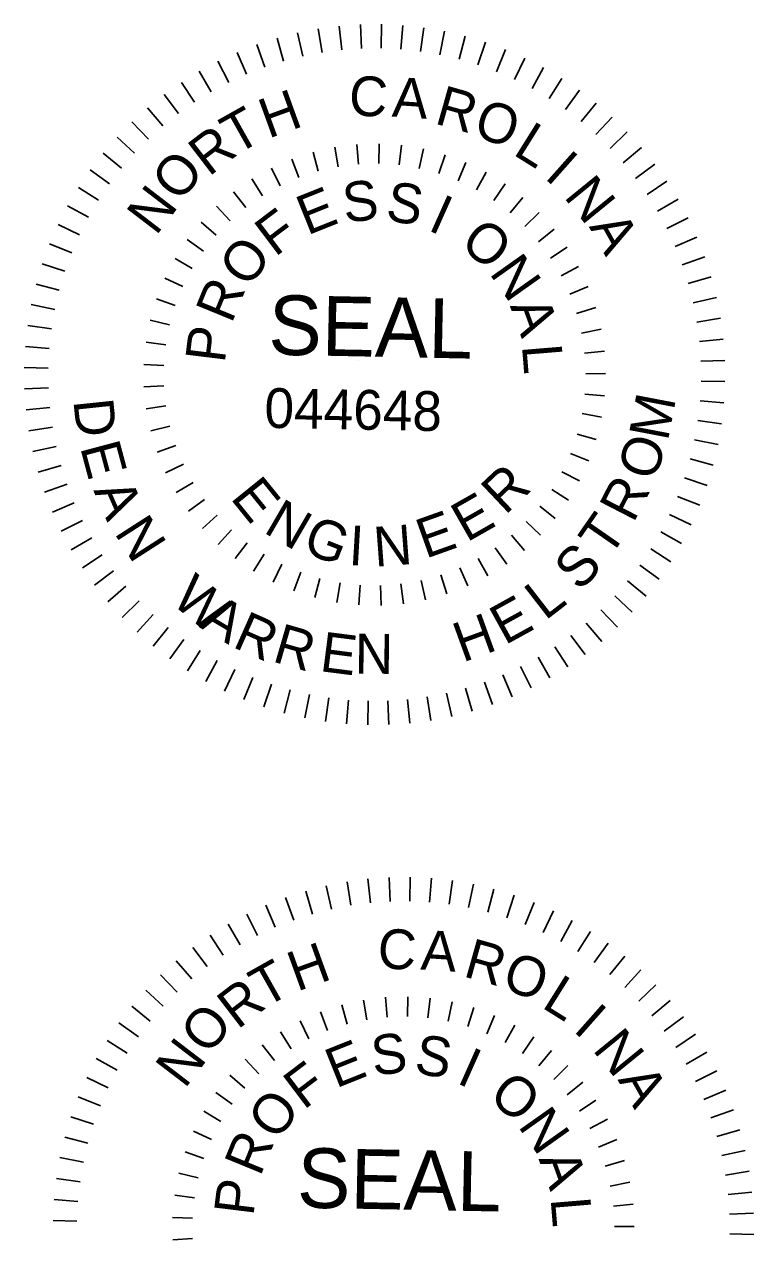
# Model space of a CAD drawing. Extents: x 0 to 4772457, y -312190 to 1506.
# Drawn here: x 3.6853 to 3.812, y 1.4541 to 1.6653 of the extents above; entities that cross this region are included whole.
import ezdxf

# ---------------------------------------------------------------- set-up
doc = ezdxf.new("R2010")
doc.units = 0
doc.layers.add('Phasing Diagram CELL', color=7, linetype='Continuous')

msp = doc.modelspace()

# ---------------------------------------------------------------- linework, layer by layer
at = {"layer": 'Phasing Diagram CELL'}
for p, q in [((3.73639, 1.66449), (3.73706, 1.6604)), ((3.74004, 1.66497), (3.74045, 1.66085)), ((3.7437, 1.66523), (3.74387, 1.66109)), ((3.74738, 1.66527), (3.7473, 1.66112)), ((3.75106, 1.66508), (3.75073, 1.66095)), ((3.75471, 1.66468), (3.75413, 1.66057)), ((3.75833, 1.66406), (3.7575, 1.65999)), ((3.72922, 1.66288), (3.73037, 1.65888)), ((3.73279, 1.66379), (3.73369, 1.65974)), ((3.76191, 1.66322), (3.76084, 1.65921)), ((3.76544, 1.66216), (3.76412, 1.65822)), ((3.7223, 1.6604), (3.72392, 1.65659)), ((3.72572, 1.66175), (3.72712, 1.65783)), ((3.76888, 1.66089), (3.76733, 1.65704)), ((3.71896, 1.65886), (3.72082, 1.65515)), ((3.77225, 1.65941), (3.77048, 1.65566)), ((3.77552, 1.65774), (3.77352, 1.6541)), ((3.71572, 1.65712), (3.7178, 1.65353)), ((3.77869, 1.65587), (3.77647, 1.65236)), ((3.7126, 1.65518), (3.71489, 1.65172)), ((3.78174, 1.65381), (3.77931, 1.65045)), ((3.7096, 1.65306), (3.71209, 1.64975)), ((3.78465, 1.65158), (3.78203, 1.64836)), ((3.70672, 1.65076), (3.70941, 1.64761)), ((3.78743, 1.64916), (3.78462, 1.64612)), ((3.704, 1.6483), (3.70687, 1.64531)), ((3.70143, 1.64567), (3.70447, 1.64286)), ((3.79006, 1.64659), (3.78707, 1.64372)), ((3.69901, 1.64289), (3.70223, 1.64027)), ((3.73547, 1.64308), (3.73639, 1.63974)), ((3.73925, 1.64393), (3.73984, 1.64052)), ((3.74309, 1.64441), (3.74336, 1.64097)), ((3.74697, 1.64452), (3.7469, 1.64107)), ((3.7469, 1.64107), (3.74697, 1.64452)), ((3.75084, 1.64426), (3.75044, 1.64083)), ((3.75466, 1.64362), (3.75393, 1.64024)), ((3.79252, 1.64387), (3.78937, 1.64118)), ((3.73179, 1.64186), (3.73303, 1.63863)), ((3.7584, 1.64262), (3.75735, 1.63933)), ((3.76204, 1.64127), (3.76067, 1.63809)), ((3.79483, 1.64099), (3.79151, 1.6385)), ((3.69678, 1.63998), (3.70014, 1.63755)), ((3.72824, 1.6403), (3.72978, 1.63721)), ((3.76552, 1.63956), (3.76386, 1.63653)), ((3.69472, 1.63693), (3.69823, 1.63471)), ((3.72486, 1.6384), (3.7267, 1.63547)), ((3.76882, 1.63753), (3.76687, 1.63467)), ((3.79694, 1.63799), (3.79349, 1.6357)), ((3.72168, 1.63618), (3.72379, 1.63344)), ((3.77191, 1.63519), (3.76969, 1.63253)), ((3.79888, 1.63487), (3.79529, 1.63279)), ((3.69285, 1.63376), (3.69649, 1.63176)), ((3.71873, 1.63367), (3.7211, 1.63115)), ((3.77476, 1.63256), (3.77229, 1.63013)), ((3.69118, 1.63049), (3.69493, 1.62871)), ((3.71603, 1.63089), (3.71863, 1.62861)), ((3.80062, 1.63163), (3.79691, 1.62977)), ((3.77734, 1.62967), (3.77466, 1.6275)), ((3.80216, 1.62829), (3.79835, 1.62667)), ((3.6897, 1.62712), (3.69355, 1.62557)), ((3.71362, 1.62786), (3.71642, 1.62583)), ((3.77964, 1.62655), (3.77675, 1.62463)), ((3.71151, 1.62461), (3.71449, 1.62286)), ((3.80351, 1.62487), (3.7996, 1.62347)), ((3.68843, 1.62367), (3.69237, 1.62236)), ((3.78161, 1.62322), (3.77856, 1.62159)), ((3.68737, 1.62015), (3.69138, 1.61908)), ((3.70972, 1.62116), (3.71286, 1.61972)), ((3.78327, 1.6197), (3.78007, 1.61839)), ((3.80464, 1.62137), (3.80065, 1.62022)), ((3.70828, 1.61756), (3.71155, 1.61643)), ((3.80555, 1.6178), (3.80151, 1.6169)), ((3.68653, 1.61657), (3.6906, 1.61574)), ((3.78457, 1.61605), (3.78125, 1.61505)), ((3.70718, 1.61385), (3.71054, 1.61303)), ((3.80625, 1.6142), (3.80216, 1.61353)), ((3.68591, 1.61295), (3.69002, 1.61237)), ((3.78551, 1.61229), (3.78212, 1.61162)), ((3.68551, 1.60929), (3.68964, 1.60896)), ((3.70646, 1.61004), (3.70988, 1.60956)), ((3.80673, 1.61055), (3.80261, 1.61014)), ((3.78609, 1.60846), (3.78265, 1.60812)), ((3.80699, 1.60689), (3.80285, 1.60672)), ((3.68532, 1.60562), (3.68947, 1.60554)), ((3.7061, 1.60618), (3.70955, 1.60602)), ((3.74334, 1.60681), (3.74334, 1.60681)), ((3.78629, 1.60459), (3.78284, 1.60457)), ((3.80703, 1.60321), (3.80288, 1.60329)), ((3.68536, 1.60194), (3.6895, 1.60211)), ((3.70611, 1.6023), (3.70956, 1.60248)), ((3.78612, 1.60072), (3.78268, 1.60103)), ((3.68562, 1.59828), (3.68974, 1.59869)), ((3.70651, 1.59845), (3.70992, 1.59896)), ((3.80685, 1.59953), (3.80271, 1.59986)), ((3.7822, 1.59765), (3.7856, 1.59701)), ((3.80644, 1.59588), (3.80234, 1.59646)), ((3.6861, 1.59463), (3.69019, 1.5953)), ((3.70727, 1.59464), (3.71062, 1.59548)), ((3.70839, 1.59093), (3.71165, 1.59209)), ((3.78467, 1.59311), (3.78135, 1.59408)), ((3.80582, 1.59226), (3.80175, 1.59309)), ((3.6868, 1.59103), (3.69085, 1.59193)), ((3.7834, 1.58945), (3.78019, 1.59073)), ((3.68771, 1.58746), (3.69171, 1.58861)), ((3.70987, 1.58735), (3.713, 1.58883)), ((3.80498, 1.58868), (3.80097, 1.58975)), ((3.78177, 1.58593), (3.77871, 1.58752)), ((3.80392, 1.58515), (3.79998, 1.58647)), ((3.68884, 1.58396), (3.69276, 1.58536)), ((3.71168, 1.58393), (3.71466, 1.58569)), ((3.77983, 1.58258), (3.77693, 1.58446)), ((3.69019, 1.58054), (3.694, 1.58216)), ((3.71382, 1.58069), (3.71661, 1.58274)), ((3.77756, 1.57943), (3.77486, 1.58158)), ((3.80265, 1.58171), (3.7988, 1.58326)), ((3.71627, 1.57768), (3.71884, 1.57998)), ((3.80117, 1.57834), (3.79742, 1.58011)), ((3.69173, 1.5772), (3.69544, 1.57906)), ((3.71898, 1.57492), (3.72133, 1.57746)), ((3.775, 1.57652), (3.77252, 1.57892)), ((3.69347, 1.57396), (3.69706, 1.57604)), ((3.72196, 1.57244), (3.72404, 1.57519)), ((3.77218, 1.57387), (3.76994, 1.5765)), ((3.7995, 1.57507), (3.79586, 1.57707)), ((3.69541, 1.57084), (3.69887, 1.57312)), ((3.72515, 1.57025), (3.72697, 1.57319)), ((3.76911, 1.5715), (3.76713, 1.57434)), ((3.79763, 1.5719), (3.79413, 1.57412)), ((3.72856, 1.56838), (3.73007, 1.57149)), ((3.76583, 1.56944), (3.76413, 1.57246)), ((3.79557, 1.56885), (3.79221, 1.57128)), ((3.69753, 1.56784), (3.70084, 1.57033)), ((3.73212, 1.56684), (3.73333, 1.57008)), ((3.73668, 1.56901), (3.73578, 1.56566)), ((3.75873, 1.56631), (3.75765, 1.5696)), ((3.76235, 1.56771), (3.76096, 1.57087)), ((3.69983, 1.56496), (3.70298, 1.56765)), ((3.7396, 1.56484), (3.74016, 1.56825)), ((3.74344, 1.56439), (3.74368, 1.56784)), ((3.74732, 1.56431), (3.74722, 1.56777)), ((3.75118, 1.56461), (3.75075, 1.56804)), ((3.755, 1.56528), (3.75424, 1.56866)), ((3.79334, 1.56594), (3.79012, 1.56856)), ((3.70229, 1.56224), (3.70528, 1.56511)), ((3.79092, 1.56316), (3.78788, 1.56597)), ((3.70492, 1.55966), (3.70773, 1.56271)), ((3.78835, 1.56053), (3.78548, 1.56352)), ((3.7077, 1.55725), (3.71032, 1.56047)), ((3.78563, 1.55807), (3.78294, 1.56122)), ((3.71061, 1.55502), (3.71304, 1.55838)), ((3.78275, 1.55577), (3.78026, 1.55908)), ((3.71366, 1.55296), (3.71588, 1.55646)), ((3.77975, 1.55365), (3.77747, 1.5571)), ((3.71683, 1.55109), (3.71883, 1.55473)), ((3.77663, 1.55171), (3.77455, 1.5553)), ((3.7201, 1.54942), (3.72188, 1.55317)), ((3.77005, 1.54843), (3.76843, 1.55224)), ((3.77339, 1.54997), (3.77153, 1.55368)), ((3.72347, 1.54794), (3.72502, 1.55179)), ((3.72692, 1.54667), (3.72823, 1.55061)), ((3.76313, 1.54595), (3.76198, 1.54994)), ((3.76663, 1.54708), (3.76523, 1.55099)), ((3.73044, 1.54561), (3.73151, 1.54962)), ((3.73402, 1.54477), (3.73485, 1.54884)), ((3.73764, 1.54415), (3.73822, 1.54825)), ((3.7413, 1.54374), (3.74163, 1.54788)), ((3.74865, 1.5436), (3.74848, 1.54774)), ((3.75231, 1.54386), (3.7519, 1.54798)), ((3.75596, 1.54434), (3.75529, 1.54843)), ((3.75957, 1.54504), (3.75866, 1.54908)), ((3.74497, 1.54356), (3.74505, 1.54771)), ((3.74138, 1.51631), (3.74204, 1.51222)), ((3.74502, 1.51679), (3.74544, 1.51266)), ((3.74869, 1.51705), (3.74885, 1.5129)), ((3.75237, 1.51709), (3.75228, 1.51294)), ((3.75604, 1.5169), (3.75571, 1.51277)), ((3.75969, 1.5165), (3.75912, 1.51239)), ((3.7342, 1.51469), (3.73536, 1.5107)), ((3.73777, 1.51561), (3.73868, 1.51156)), ((3.76332, 1.51588), (3.76249, 1.51181)), ((3.76689, 1.51503), (3.76583, 1.51102)), ((3.77042, 1.51398), (3.76911, 1.51003)), ((3.72729, 1.51222), (3.72891, 1.5084)), ((3.73071, 1.51356), (3.73211, 1.50965)), ((3.77387, 1.51271), (3.77232, 1.50886)), ((3.72395, 1.51068), (3.7258, 1.50696)), ((3.77723, 1.51123), (3.77546, 1.50748)), ((3.72071, 1.50893), (3.72279, 1.50534)), ((3.78051, 1.50956), (3.77851, 1.50592)), ((3.78368, 1.50769), (3.78146, 1.50418)), ((3.71758, 1.507), (3.71987, 1.50354)), ((3.78672, 1.50563), (3.7843, 1.50226)), ((3.71458, 1.50488), (3.71707, 1.50157)), ((3.78964, 1.50339), (3.78702, 1.50018)), ((3.71171, 1.50258), (3.7144, 1.49942)), ((3.70898, 1.50011), (3.71186, 1.49712)), ((3.79242, 1.50098), (3.78961, 1.49793)), ((3.70641, 1.49749), (3.70946, 1.49468)), ((3.79504, 1.49841), (3.79205, 1.49554)), ((3.74424, 1.49575), (3.74483, 1.49234)), ((3.74808, 1.49623), (3.74834, 1.49278)), ((3.75196, 1.49634), (3.75189, 1.49289)), ((3.75189, 1.49289), (3.75196, 1.49634)), ((3.75583, 1.49607), (3.75542, 1.49264)), ((3.75965, 1.49544), (3.75892, 1.49206)), ((3.79751, 1.49568), (3.79435, 1.493)), ((3.704, 1.49471), (3.70721, 1.49209)), ((3.73677, 1.49368), (3.73801, 1.49045)), ((3.74046, 1.4949), (3.74138, 1.49156)), ((3.76339, 1.49444), (3.76234, 1.49114)), ((3.76702, 1.49308), (3.76566, 1.4899)), ((3.70176, 1.4918), (3.70513, 1.48937)), ((3.73323, 1.49212), (3.73477, 1.48902)), ((3.7705, 1.49138), (3.76884, 1.48835)), ((3.79981, 1.49281), (3.79649, 1.49032)), ((3.69971, 1.48875), (3.70321, 1.48653)), ((3.72984, 1.49022), (3.73168, 1.48728)), ((3.77381, 1.48935), (3.77186, 1.48649)), ((3.80193, 1.48981), (3.79847, 1.48752)), ((3.72666, 1.488), (3.72878, 1.48526)), ((3.7769, 1.48701), (3.77468, 1.48435)), ((3.80386, 1.48669), (3.80027, 1.4846)), ((3.69783, 1.48558), (3.70147, 1.48358)), ((3.72371, 1.48549), (3.72608, 1.48296)), ((3.69617, 1.4823), (3.69991, 1.48053)), ((3.72102, 1.4827), (3.72361, 1.48042)), ((3.77974, 1.48438), (3.77728, 1.48195)), ((3.80561, 1.48344), (3.80189, 1.48159)), ((3.78233, 1.48149), (3.77964, 1.47931)), ((3.69468, 1.47894), (3.69854, 1.47739)), ((3.7186, 1.47967), (3.72141, 1.47765)), ((3.78462, 1.47836), (3.78174, 1.47645)), ((3.80715, 1.48011), (3.80333, 1.47848)), ((3.7165, 1.47642), (3.71948, 1.47467)), ((3.80849, 1.47668), (3.80458, 1.47529)), ((3.69342, 1.47549), (3.69736, 1.47418)), ((3.7866, 1.47503), (3.78355, 1.47341)), ((3.69236, 1.47196), (3.69637, 1.4709)), ((3.71471, 1.47298), (3.71785, 1.47154)), ((3.80962, 1.47319), (3.80563, 1.47203)), ((3.78825, 1.47152), (3.78505, 1.4702)), ((3.81054, 1.46962), (3.80649, 1.46872)), ((3.69152, 1.46839), (3.69558, 1.46756)), ((3.71326, 1.46938), (3.71653, 1.46825)), ((3.78955, 1.46787), (3.78624, 1.46687)), ((3.71217, 1.46566), (3.71553, 1.46485)), ((3.81124, 1.46601), (3.80714, 1.46535)), ((3.6909, 1.46476), (3.695, 1.46419)), ((3.7905, 1.46411), (3.78711, 1.46343)), ((3.71144, 1.46185), (3.71486, 1.46138)), ((3.81172, 1.46237), (3.80759, 1.46195)), ((3.69049, 1.46111), (3.69462, 1.46078)), ((3.79107, 1.46028), (3.78764, 1.45993)), ((3.69031, 1.45744), (3.69445, 1.45736)), ((3.71108, 1.45799), (3.71453, 1.45784)), ((3.74833, 1.45863), (3.74833, 1.45863)), ((3.81198, 1.4587), (3.80783, 1.45854)), ((3.79128, 1.45641), (3.78782, 1.45639)), ((3.81202, 1.45503), (3.80787, 1.45511)), ((3.7111, 1.45412), (3.71455, 1.4543))]:
    msp.add_line(p, q, dxfattribs=at)

# ---------------------------------------------------------------- texts
for s, height, rotation, p in [('C', 0.00691, 356.2217, (3.74154, 1.64954)), ('A', 0.00691, 356.2217, (3.74909, 1.64925)), ('H', 0.00691, 19.9324, (3.72771, 1.64537)), ('R', 0.00691, 344.2124, (3.75639, 1.64809)), ('O', 0.00691, 341.1556, (3.76304, 1.64597)), ('T', 0.00691, 29.3644, (3.72208, 1.64248)), ('R', 0.00691, 37.5253, (3.71736, 1.6387)), ('L', 0.00691, 328.0193, (3.77001, 1.64275)), ('I', 0.00691, 318.4439, (3.7755, 1.63863)), ('O', 0.00691, 50.5821, (3.71227, 1.63415)), ('N', 0.00691, 309.1494, (3.77889, 1.63531)), ('N', 0.00691, 52.5415, (3.70818, 1.62839)), ('E', 0.00691, 21.8091, (3.73446, 1.62855)), ('S', 0.00691, 6.5129, (3.741, 1.63079)), ('S', 0.00691, 351.2166, (3.74791, 1.63123)), ('I', 0.00691, 335.9204, (3.75522, 1.62959)), ('F', 0.00691, 37.1054, (3.72886, 1.62475)), ('O', 0.00691, 320.6242, (3.76074, 1.62679)), ('A', 0.00691, 299.3819, (3.78335, 1.63012)), ('O', 0.00691, 52.4016, (3.72415, 1.61927)), ('N', 0.00691, 305.3279, (3.76597, 1.62206)), ('R', 0.00691, 67.6979, (3.7213, 1.61312)), ('SEAL', 0.010372, 358.8648, (3.72766, 1.60789)), ('A', 0.00691, 290.0317, (3.76965, 1.61633)), ('P', 0.00691, 82.9941, (3.72012, 1.60629)), ('L', 0.00691, 274.7354, (3.77175, 1.60945)), ('044648', 0.006909, 358.8648, (3.72698, 1.59519)), ('M', 0.00691, 79.1773, (3.7971, 1.59272)), ('D', 0.00691, 275.9811, (3.69383, 1.59991)), ('E', 0.00691, 284.9836, (3.69499, 1.59181)), ('O', 0.00691, 71.1829, (3.79472, 1.58569)), ('R', 0.00691, 43.4297, (3.76884, 1.57988)), ('E', 0.00691, 308.9349, (3.72098, 1.58297)), ('R', 0.00691, 62.7337, (3.79111, 1.57847)), ('A', 0.00691, 293.8062, (3.69729, 1.58429)), ('E', 0.00691, 29.6586, (3.76216, 1.5752)), ('N', 0.00691, 329.7899, (3.72667, 1.57709)), ('N', 0.00691, 302.6889, (3.70085, 1.57695)), ('G', 0.00691, 338.5562, (3.73337, 1.57372)), ('E', 0.00691, 19.6727, (3.75501, 1.57239)), ('T', 0.00691, 55.228, (3.78693, 1.57238)), ('I', 0.00691, 356.651, (3.74155, 1.57135)), ('N', 0.00691, 4.2806, (3.74623, 1.57102)), ('S', 0.00691, 46.5552, (3.78179, 1.56658)), ('W', 0.00691, 320.3641, (3.71061, 1.56485)), ('L', 0.00691, 37.7626, (3.7758, 1.56158)), ('A', 0.00691, 329.3125, (3.71556, 1.56059)), ('E', 0.00691, 28.88, (3.76879, 1.55734)), ('R', 0.00691, 336.0279, (3.72128, 1.55716)), ('H', 0.00691, 19.9974, (3.76146, 1.55436)), ('R', 0.00691, 343.8077, (3.7282, 1.55463)), ('E', 0.00691, 352.7158, (3.73649, 1.55292)), ('N', 0.00691, 359.3001, (3.74269, 1.55249)), ('C', 0.00691, 356.2217, (3.74653, 1.50136)), ('A', 0.00691, 356.2217, (3.75407, 1.50107)), ('H', 0.00691, 19.9324, (3.73269, 1.49719)), ('R', 0.00691, 344.2124, (3.76137, 1.49991)), ('O', 0.00691, 341.1556, (3.76802, 1.49779)), ('T', 0.00691, 29.3644, (3.72707, 1.49429)), ('L', 0.00691, 328.0193, (3.77499, 1.49457)), ('R', 0.00691, 37.5253, (3.72235, 1.49052)), ('I', 0.00691, 318.4439, (3.78048, 1.49045)), ('O', 0.00691, 50.5821, (3.71725, 1.48597)), ('N', 0.00691, 309.1494, (3.78388, 1.48712)), ('N', 0.00691, 52.5415, (3.71317, 1.48021)), ('E', 0.00691, 21.8091, (3.73945, 1.48037)), ('S', 0.00691, 6.5129, (3.74598, 1.48261)), ('S', 0.00691, 351.2166, (3.75289, 1.48305)), ('I', 0.00691, 335.9204, (3.76021, 1.48141)), ('F', 0.00691, 37.1054, (3.73384, 1.47657)), ('O', 0.00691, 320.6242, (3.76572, 1.47861)), ('A', 0.00691, 299.3819, (3.78834, 1.48193)), ('O', 0.00691, 52.4016, (3.72914, 1.47109)), ('N', 0.00691, 305.3279, (3.77095, 1.47388)), ('R', 0.00691, 67.6979, (3.72628, 1.46494)), ('SEAL', 0.010372, 358.8648, (3.73264, 1.45971)), ('A', 0.00691, 290.0317, (3.77463, 1.46815)), ('P', 0.00691, 82.9941, (3.7251, 1.45811)), ('L', 0.00691, 274.7354, (3.77673, 1.46126))]:
    msp.add_text(s, height=height, rotation=rotation, dxfattribs=at).set_placement(p)

doc.saveas('drawing.dxf')
